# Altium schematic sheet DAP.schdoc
size 297 x 209 mm; Symbol: Drawing-Symbol_A4; Company: 嘉立创EDA; Version: V1.0; Page Size: A4; @Project Name: HPM5E3YIVK1; @Update Date: 2026-07-31; @Create Date: 2026-07-31; Device: Drawing-Symbol_A4; @Board Name: HPM5E3YIVK1_1; @Page Name: P1; @Create Time: 23:53:32; @Page Count: 9; @Page No: 9; @Schematic Name: HPM5E3YIVK1_1; @Update Time: 23:53:32; @Assembly Variant: Basic; Border: 1; Title Block Position: 3; Size: A4; Width: 1170; Height: 825; Region Start: 1; X Region Count: 6; Y Region Count: 4; Blade Width: 10
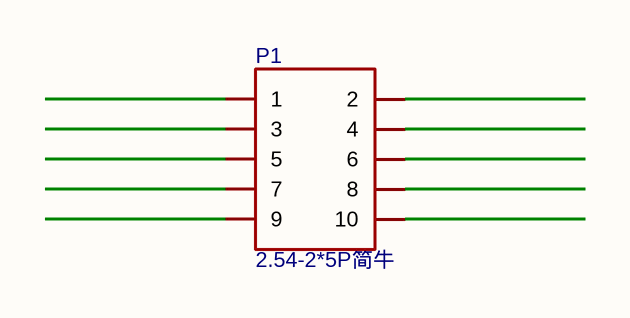
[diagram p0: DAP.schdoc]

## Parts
P1  2.54-2*5P简牛  [IDC-TH_10P-P2.54_C5665]

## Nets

Not connected (* = marked no-connect by the designer): P1 1 2 3 4 5 6 7 8 9 10

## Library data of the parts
P1 = 2.54-2*5P简牛: 连接器类型:简牛座;间距:2.54mm;结构:2x5P;额定电流:1A;安装方式:直插;行距:2.54mm;排数:2;每排PIN数:5;触头材质:黄铜;触头镀层:金;工作温度:-55℃~+105℃;; Manufacturer: BOOMELE(博穆精密); Symbol: HDR-IDC-2.54-2X5P; AddInBom: yes; ModelId: 1d28e50a904749439e5167098e48e9840819f05c4eef4c71ace90d822a990e87; ModelTransform: 799.998,348.41478,0,0,0,0,0,3.937,-118.11; Connector Type: 简牛座; Pitch: 2.54mm; Number of Positions or Pins: 2x5P; Current Rating: 1A; Holder Type: 直插; Number of PINs Per Row: 5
